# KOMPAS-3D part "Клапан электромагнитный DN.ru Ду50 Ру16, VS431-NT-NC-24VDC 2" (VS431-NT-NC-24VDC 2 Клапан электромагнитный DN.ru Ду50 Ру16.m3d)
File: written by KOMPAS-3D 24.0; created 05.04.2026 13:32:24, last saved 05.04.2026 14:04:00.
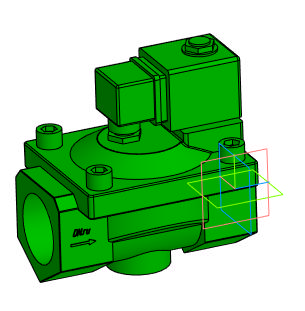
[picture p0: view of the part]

Document properties: Автор: artio; Полное имя файла: C:\Users\artio\OneDrive\Рабочий стол\Клапан электромагнитный DN.ru\VS431\VS431-NT-NC\VS431-NT-NC-24VDC\Ду50\VS431-NT-NC-24VDC 2 Клапан электромагнитный DN.ru Ду50 Ру16.m3d

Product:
- Body: Тело 1  | qty 1
    Масса: 6.703651
- Part/product: Клапан электромагнитный DN.ru Ду50 Ру16  | designation VS431-NT-NC-24VDC 2
    Масса: 3.341
    Раздел спецификации: Прочие изделия
    Примечание: D130-04752
    additional columns: ef56311e-7521-43dc-8291-0e6108b3d81d; artio; c; Шероховатость не задана; Да

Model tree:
1. Операция без истории:1

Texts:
  VS431-NT-NC-24VDC 2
